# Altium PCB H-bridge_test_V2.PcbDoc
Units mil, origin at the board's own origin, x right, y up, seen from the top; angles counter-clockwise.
Board outline 3085 x 1190 mil, 2 copper layers (Top Layer, Bottom Layer); 22 components, 22 nets, 82 pads, 14 vias.
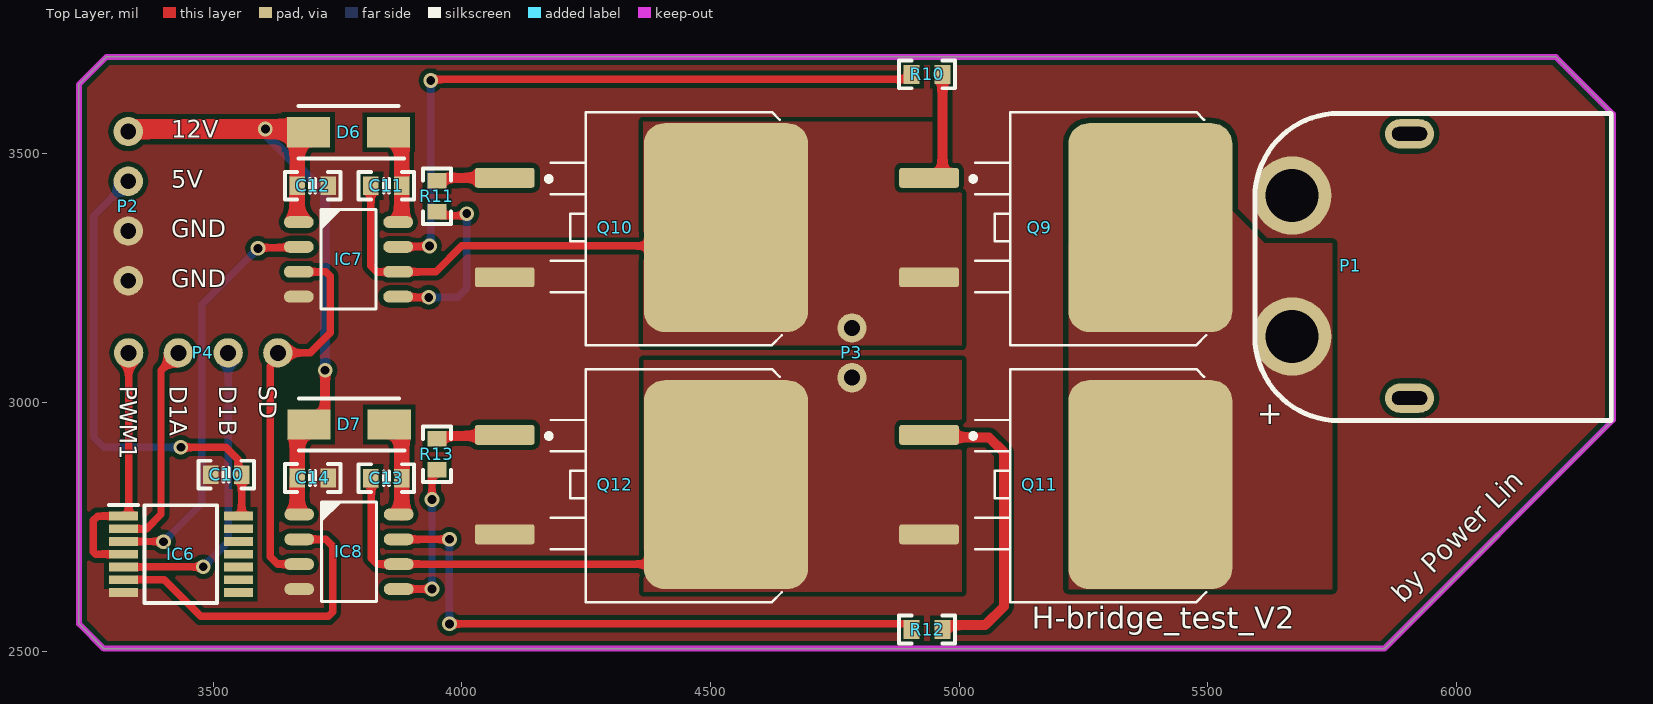
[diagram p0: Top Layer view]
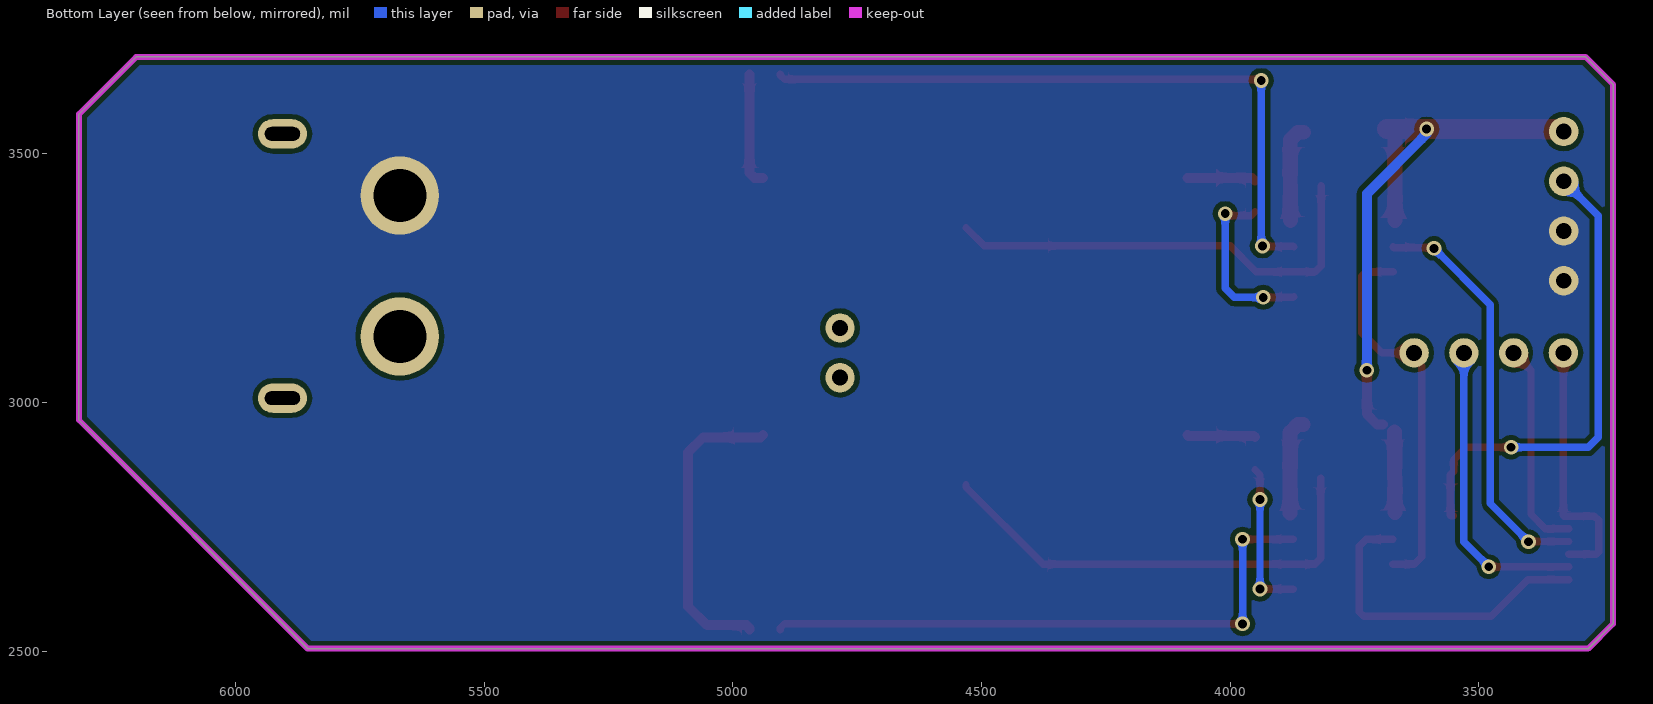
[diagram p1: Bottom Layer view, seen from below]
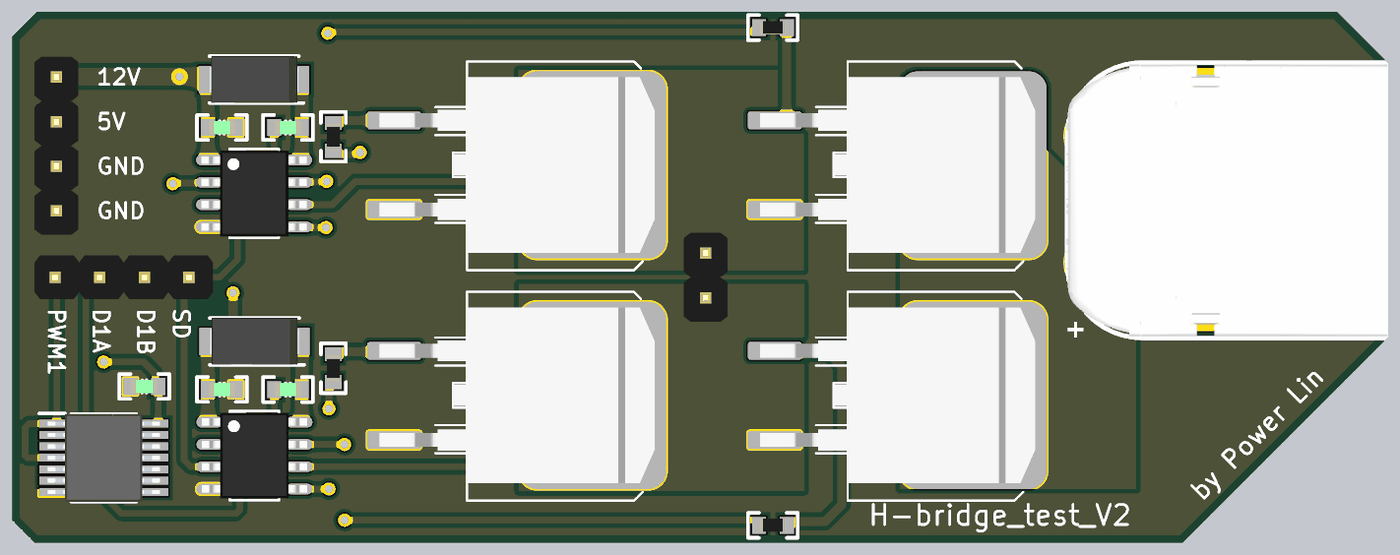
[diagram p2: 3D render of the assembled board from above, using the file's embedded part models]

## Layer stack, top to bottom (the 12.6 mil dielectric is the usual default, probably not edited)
Top Solder: solder mask 0.4, Solder Resist, Dk 3.5
Top Layer: signal copper 1.4
Dielectric 1: dielectric 12.6, FR-4, Dk 4.8
Bottom Layer: signal copper 1.4
Bottom Solder: solder mask 0.4, Solder Resist, Dk 3.5

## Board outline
3230,2555 3280,2505 5855,2505 6315,2965 6315,3580 6200,3695 3285,3695 3230,3640

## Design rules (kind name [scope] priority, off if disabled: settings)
Clearance [All] p1: gap=10 ignorepadtopadclearanceinfootprint=FALSE except(0: Arc-Hole Track-Hole SMDPad-Hole THPad-Hole Via-Hole Fill-Hole Poly-Hole Region-Hole Text-Hole)
PlaneConnect [All] p1: planeconnectstyle=Direct reliefexpansion=20 reliefentries=4 reliefconductorwidth=10 reliefairgap=10
PolygonConnect [All] p1: connectstyle=Direct reliefconductorwidth=10 reliefentries=4 polygonreliefangle="90 Angle" airgapwidth=10
RoutingVias [All] p1: holewidth=17.72 width=29.53 viastyle="Through Hole" minholewidth=17.72 minwidth=29.53 maxholewidth=17.72 maxwidth=29.53
SolderMaskExpansion [All] p1: expansion=4 istentingtop=FALSE
Width [All] p1: maxlimit=100 minlimit=15 preferedwidth=15
29 further rules are at their usual default settings.

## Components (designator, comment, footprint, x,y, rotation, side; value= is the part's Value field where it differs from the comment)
C10 "100nF" CAP-0603 3526.1,2855 r0 top
C11 "1uF/25V" CAP-0603 3848.07,3435.95 r180 top
C12 "100nF" CAP-0603 3700,3435.95 r180 top
C13 "1uF/25V" CAP-0603 3848.12,2847.94 r180 top
C14 "100nF" CAP-0603 3700,2848.3 r180 top
D6 "SS14" DO-214AC_SMA 3772.07,3543.64 r180 top
D7 "SS14" DO-214AC_SMA 3773.21,2956 r180 top
IC6 "SN74HC08PW" TSSOP14 3435,2695 r0 top
IC7 "IR2104S" SOIC_8 3772.07,3288 r270 top
IC8 "IR2104S" SOIC_8 3773,2700 r270 top
P1 "XT30" XT60PW-M 5669.65,3416.38 r270 top
P2 "HDR1x4_2.54" HDR1x4_2.54_180 3329.18,3545 r0 top
P3 "HDR1x2_2.54" HDR1X2_2.54_180 4784.54,3150 r0 top
P4 "HDR1x4_2.54" HDR1x4_2.54_180 3330,3100 r90 top
Q9 "IRF3205S" D2PAK-3 5162.01,3351.95 r180 top
Q10 "IRF3205S" D2PAK-3 4308.64,3351.95 r180 top
Q11 "IRF3205S" D2PAK-3 5162.01,2835 r180 top
Q12 "IRF3205S" D2PAK-3 4308.64,2835 r180 top
R10 "51R" R-0603 4935.45,3660 r0 top
R11 "51R" R-0603 3950,3415 r90 top
R12 "51R" R-0603 4935.45,2543.52 r0 top
R13 "51R" R-0603 3950,2896 r90 top

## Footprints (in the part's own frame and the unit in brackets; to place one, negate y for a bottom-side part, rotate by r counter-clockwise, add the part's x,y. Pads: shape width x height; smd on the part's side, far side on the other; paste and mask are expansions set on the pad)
CAP-0603 [mm]
  rect 0.8x0.96 smd: 1(-0.79,0) 2(0.79,0)
  silkscreen extent -1.42,-0.71 1.42,0.71, body extent -0.76,-0.39 0.76,0.39, height 0.9
D2PAK-3 [mil] "D-PAK/TO-263-3; 3 Leads (1 Cropped); Body 14.7 (inc. leads) x 10.2 mm (LxW max)"
  round 20 on Mech15: 0(0,0)
  rrect25% 120x40 smd: 1(222.5,-100) 2(222.5,100)
  rrect25% 330x420 smd: 3(-222.5,0)
  silkscreen extent -335,-232 139,236, body extent -361,-197 256,197, height 189
DO-214AC_SMA [mm]
  rect 2.2x1.55 smd: 1(2.05,0) 2(-2.05,0)
  silkscreen extent -2.83,-1.33 2.55,1.33, body extent -2.55,-1.33 2.55,1.33, height 2.29
HDR1X2_2.54_180 [mm]
  round 1.5 hole 0.813: 1(0,0) 2(0,-2.54)
  body extent -1.25,-3.81 1.25,1.27, height 8.2
HDR1x4_2.54_180 [mm]
  round 1.5 hole 0.813: 1(0,0) 2(0,-2.54) 3(0,-5.08) 4(0,-7.62)
  body extent -1.25,-8.89 1.25,1.27, height 8.2
R-0603 [mm]
  rect 0.8x0.96 smd: 1(-0.79,0) 2(0.79,0)
  silkscreen extent -1.42,-0.71 1.42,0.71, body extent -0.76,-0.38 0.76,0.38, height 0.41
SOIC_8 [mil]
  oval 24x60 smd: 1(-75,-100.02) 2(-25,-100.02) 3(25,-100.02) 4(75,-100.02) 5(75,99.98) 6(25,99.98) 7(-25,99.98) 8(-75,99.98)
  silkscreen extent -100,-55 100,55, body extent -96,-118 96,118, height 69
TSSOP14 [mm]
  rect 1.475x0.45 smd: 1(-2.938,1.95) 2(-2.938,1.3) 3(-2.938,0.65) 4(-2.938,0) 5(-2.938,-0.65) 6(-2.938,-1.3) 7(-2.938,-1.95) 8(2.938,-1.95) 9(2.938,-1.3) 10(2.938,-0.65) 11(2.938,0) 12(2.938,0.65) 13(2.938,1.3) 14(2.938,1.95)
  silkscreen extent -3.67,-2.5 1.85,2.52, body extent -3.2,-2.5 3.2,2.5, height 1.2
XT60PW-M [mm]
  oval 1.5x2.5 hole 0.7 slot 1.8 at 90 deg: 0(-3.15,6) 0(10.35,6)
  round 4 hole 2.7: 1(7.2,0) 2(0,0)
  silkscreen extent -4.2,-1.9 11.5,16.3, body extent -4.3,-1.95 11.6,16.35, height 8.45

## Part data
C10 C11 C12 C13 C14: library part CAP, "贴片电容", Package=0402, SuppliersPartNumber=C52923
D6 D7: library part DIODE, "二极管", Package=SMA(DO-214AC), SuppliersPartNumber=C22452
IC6: "Integrated Circuit", Arrow Part Number=SN74HCT08PW, Manufacturer_Name="Texas Instruments", Mouser Part Number=595-SN74HCT08PW
IC7 IC8: "Integrated Circuit", Manufacturer_Name=Infineon
P1: library part XT30/60, "XT30/60"
P2 P3 P4: "Header"
Q9 Q10 Q11 Q12: library part N-MOS, "N 沟道 MOS", Manufacturer_Name=Nexperia, Manufacturer_Part_Number=SI2302DS, Mouser Part Number=N/A, RS Part Number=7983053P
R10 R11 R12 R13: library part RES, "贴片电阻", Package=0805, SuppliersPartNumber=C17798

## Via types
v1: diameter 29.53, hole 17.72, Top Layer to Bottom Layer, 14 vias

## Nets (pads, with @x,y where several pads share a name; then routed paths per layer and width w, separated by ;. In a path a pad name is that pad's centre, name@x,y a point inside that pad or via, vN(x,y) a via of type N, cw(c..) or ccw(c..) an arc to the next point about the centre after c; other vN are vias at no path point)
5V: C10.2 IC6.14 P2.2 | length 973.2
  Top Layer w15: v1(3435,2910) 3525,2910 3550.37,2884.63 3550.37,2861.83 C10.2 3557.2,2773.13 3556.61,2772.54 IC6.14@3551.44,2772.54
  Bottom Layer w15: P2.2 3260,3375.82 3260,2930 3280,2910 v1(3435,2910)
12V: C12.2 C14.2 D6.1 D7.1 IC7.1 IC8.1 P2.1 | length 1355.5
  Top Layer w20: D6.1@3685,3550 D6.1 ; D7.1 3704.49,2956 3725,2976.51 v1(3725,3065)
  Top Layer w30: IC7.1@3668.73,3366 3668.73,3435.78 C12.2 D6.1@3668.9,3528.13 ; IC8.1@3668.9,2778.53 C14.2 3669.07,2848.48 D7.1@3669.07,2940.66
  Top Layer w40: P2.1 3332.83,3548.65 3346.3,3548.65 3347.66,3550 v1(3604.92,3550) D6.1@3685,3550
  Bottom Layer w20: v1(3604.92,3550) 3604.92,3540.08 3725,3420 v1(3725,3065)
DIR1A: IC6.2 P4.2 | length 427.1
  Top Layer w15: IC6.2 3366.18,2746.18 3395,2775 3395,3065 P4.2
DIR1B: IC6.5 P4.3 | length 611.6
  Top Layer w15: IC6.5 3479.41,2669.41 v1(3480,2670)
  Bottom Layer w15: v1(3480,2670) 3530,2720 P4.3
FUSE: C10.1 C12.1 C14.1 IC6.7 IC7.4 IC8.4 P1.2 P2.3 P2.4 Q10.2 Q12.2
M1A: C11.2 IC7.6 P3.1 Q9.2 Q10.3 | length 916.9
  Top Layer w15: C11.2 3816.97,3275.03 3829,3263 IC7.6 3948,3263 4000,3315 4494.2,3315 Q10.3
M1B: C13.2 IC8.6 P3.2 Q11.2 Q12.3 | length 948.4
  Top Layer w15: C13.2@3817.9,2847.94 3817.9,2687.03 3829.93,2675 IC8.6 4376.21,2675 4531.14,2829.93 Q12.3
NetC11_1: C11.1 D6.2 IC7.8 | length 195
  Top Layer w30: D6.2 3863.66,3543.64 3879.17,3528.13 C11.1 3879,3435.78 IC7.8@3879,3366
NetC13_1: C13.1 D7.2 IC8.8 | length 195
  Top Layer w30: D7.2@3853,2955.81 3863.88,2955.81 3879.39,2940.3 3879.39,2848.12 C13.1 IC8.8@3879.22,2778.17
NetIC7_5: IC7.5 R11.1 | length 361.4
  Top Layer w15: IC7.5 3873.55,3211.5 v1(3933.5,3211.5) ; R11.1 3958.25,3375.65 4005.65,3375.65 v1(4010,3380)
  Bottom Layer w15: v1(3933.5,3211.5) 3991.5,3211.5 4010,3230 v1(4010,3380)
NetIC7_7: IC7.7 R10.1 | length 1370.4
  Top Layer w15: IC7.7 3873.05,3314 3934,3314 v1(3935,3315) ; v1(3937.5,3647.5) 3940,3650 4896.1,3650 4904.34,3658.25 R10.1
  Bottom Layer w15: v1(3935,3315) 3937.5,3317.5 v1(3937.5,3647.5)
NetIC8_5: IC8.5 R13.1 | length 311.1
  Top Layer w15: IC8.5 3935,2625 v1(3940,2625) ; v1(3940,2805) 3940,2854.9 R13.1
  Bottom Layer w15: v1(3940,2625) v1(3940,2805)
NetIC8_7: IC8.7 R12.1 | length 1208
  Top Layer w15: IC8.7 v1(3975,2725) ; v1(3975,2555) 4001,2555 4887.31,2555 4887.39,2554.92 4896.1,2554.92 4904.34,2546.67 R12.1
  Bottom Layer w15: v1(3975,2555) v1(3975,2725)
NetQ9_1: Q9.1 R10.2 | length 229.2
  Top Layer w20: Q9.1 4956.55,3451.95 4966.55,3461.95 R10.2
NetQ10_1: Q10.1 R11.2 | length 138.6
  Top Layer w20: R11.2 3955.75,3451.85 3996.05,3451.85 3996.14,3451.95 Q10.1
NetQ11_1: Q11.1 R12.2 | length 619.5
  Top Layer w20: Q11.1 4944.51,2930 5060,2930 5090,2900 5090,2590 5052.42,2552.42 4972.3,2552.42 4966.55,2546.67 R12.2
NetQ12_1: Q12.1 R13.2 | length 137.8
  Top Layer w20: R13.2@3950,2931.1 3951.95,2933.05 4084.19,2933.05 Q12.1
PWM1: IC6.1 IC6.4 P4.1 | length 527.9
  Top Layer w15: IC6.4 3263.79,2695 3258.79,2700 3258.79,2762.98 3267.57,2771.77 IC6.1 3328.64,2771.77 3330,2773.13 P4.1
PWM1A: IC6.3 IC7.2 | length 832.9
  Top Layer w15: IC6.3 3399.41,2720.59 v1(3400,2720) ; v1(3590,3310) 3591.5,3311.5 3670.55,3311.5 IC7.2
  Bottom Layer w15: v1(3400,2720) 3477.03,2797.03 3477.03,3197.03 v1(3590,3310)
PWM1B: IC6.6 IC8.2 | length 660
  Top Layer w15: IC6.6 3401.18,2643.82 3475,2570 3731.21,2570 3740,2578.79 3740,2711.21 3726.22,2725 IC8.2
SD: IC7.3 IC8.3 P4.4 | length 782.8
  Top Layer w15: IC7.3 3726.21,3263 3735,3254.21 3735,3140 3695,3100 P4.4 3630,3088.08 3615,3073.08 3615,2690 3630,2675 IC8.3
VM: P1.1 Q9.3 Q11.3
pads on no net: IC6.8 IC6.9 IC6.10 IC6.11 IC6.12 IC6.13 P1.0 Q9.0 Q10.0 Q11.0 Q12.0

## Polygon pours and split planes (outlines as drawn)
FUSE on Top Layer "NONET_L01_P-001" (solid, remove dead copper, pour order 4): 3069.78,4666.42 3079.78,4656.42 3079.78,2266.42 7149.78,2266.42 7329.78,2446.42 7259.78,2516.42 7259.78,4926.42
VM on Top Layer "NONET_L01_P-001" (solid, pour order 3): 5545,3390 5620,3315 5545,3315
VM on Top Layer "NONET_L01_P-001" (solid, pour order 2): 5750,2625 5750,3320 5220,3320 5220,2625
M1B on Top Layer "NONET_L01_P-001" (solid, pour order 1): 5005.46,2620 5005.46,3085 4365.46,3085 4365.46,2620
M1A on Top Layer "NONET_L01_P-001" (solid, pour order 0): 5005,3115 5005,3565 4365,3565 4365,3115
FUSE on Bottom Layer "NONET_L01_P-001" (solid, remove dead copper, pour order 5): 2699.78,4666.42 2709.78,4656.42 2709.78,2266.42 6779.78,2266.42 6959.78,2446.42 6889.78,2516.42 6889.78,4926.42

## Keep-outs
Keep-Out Layer:
  lines w12: 3230,2555 3280,2505 5855,2505 6315,2965 6315,3515 6315,3580 6200,3695 3285,3695 3230,3640 3230,2555

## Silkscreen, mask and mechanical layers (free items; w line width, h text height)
Top Overlay:
  text "12V" at 3415.91,3532.29 h35.43
  text "5V" at 3415.91,3432.29 h35.43
  text "GND" at 3415.91,3332.29 h35.43
  text "GND" at 3415.91,3232.29 h35.43
  text "PWM1" at 3312.29,3034.09 h35.43 r270
  text "D1A" at 3412.29,3034.09 h35.43 r270
  text "D1B" at 3512.29,3034.09 h35.43 r270
  text "SD" at 3592.29,3034.09 h35.43 r270
  text "by Power Lin" at 5893.6,2594.75 h40 r45
  text "H-bridge_test_V2" at 5145.91,2545 h45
